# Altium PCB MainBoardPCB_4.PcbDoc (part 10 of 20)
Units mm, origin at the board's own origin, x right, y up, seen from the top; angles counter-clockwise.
Board outline 333.63 x 349.38 mm, 16 copper layers (L1, L2 (GND), L3 (Sign), L4 (GND), L5 (Sign), L6 (PWR/GND), L7(PWR/GND), L8 (Plane_GND), L9 (PWR/GND), L10 (PWR/GND), L11 (PWR/GND), L12 (Sign), L13 (GND), L14 (Sign), L15 (GND), L16), stack 2.502 mm thick; 2205 components, 1648 nets, 8314 pads, 3172 vias.
Unrouted connection lines stored in the file: 5141.
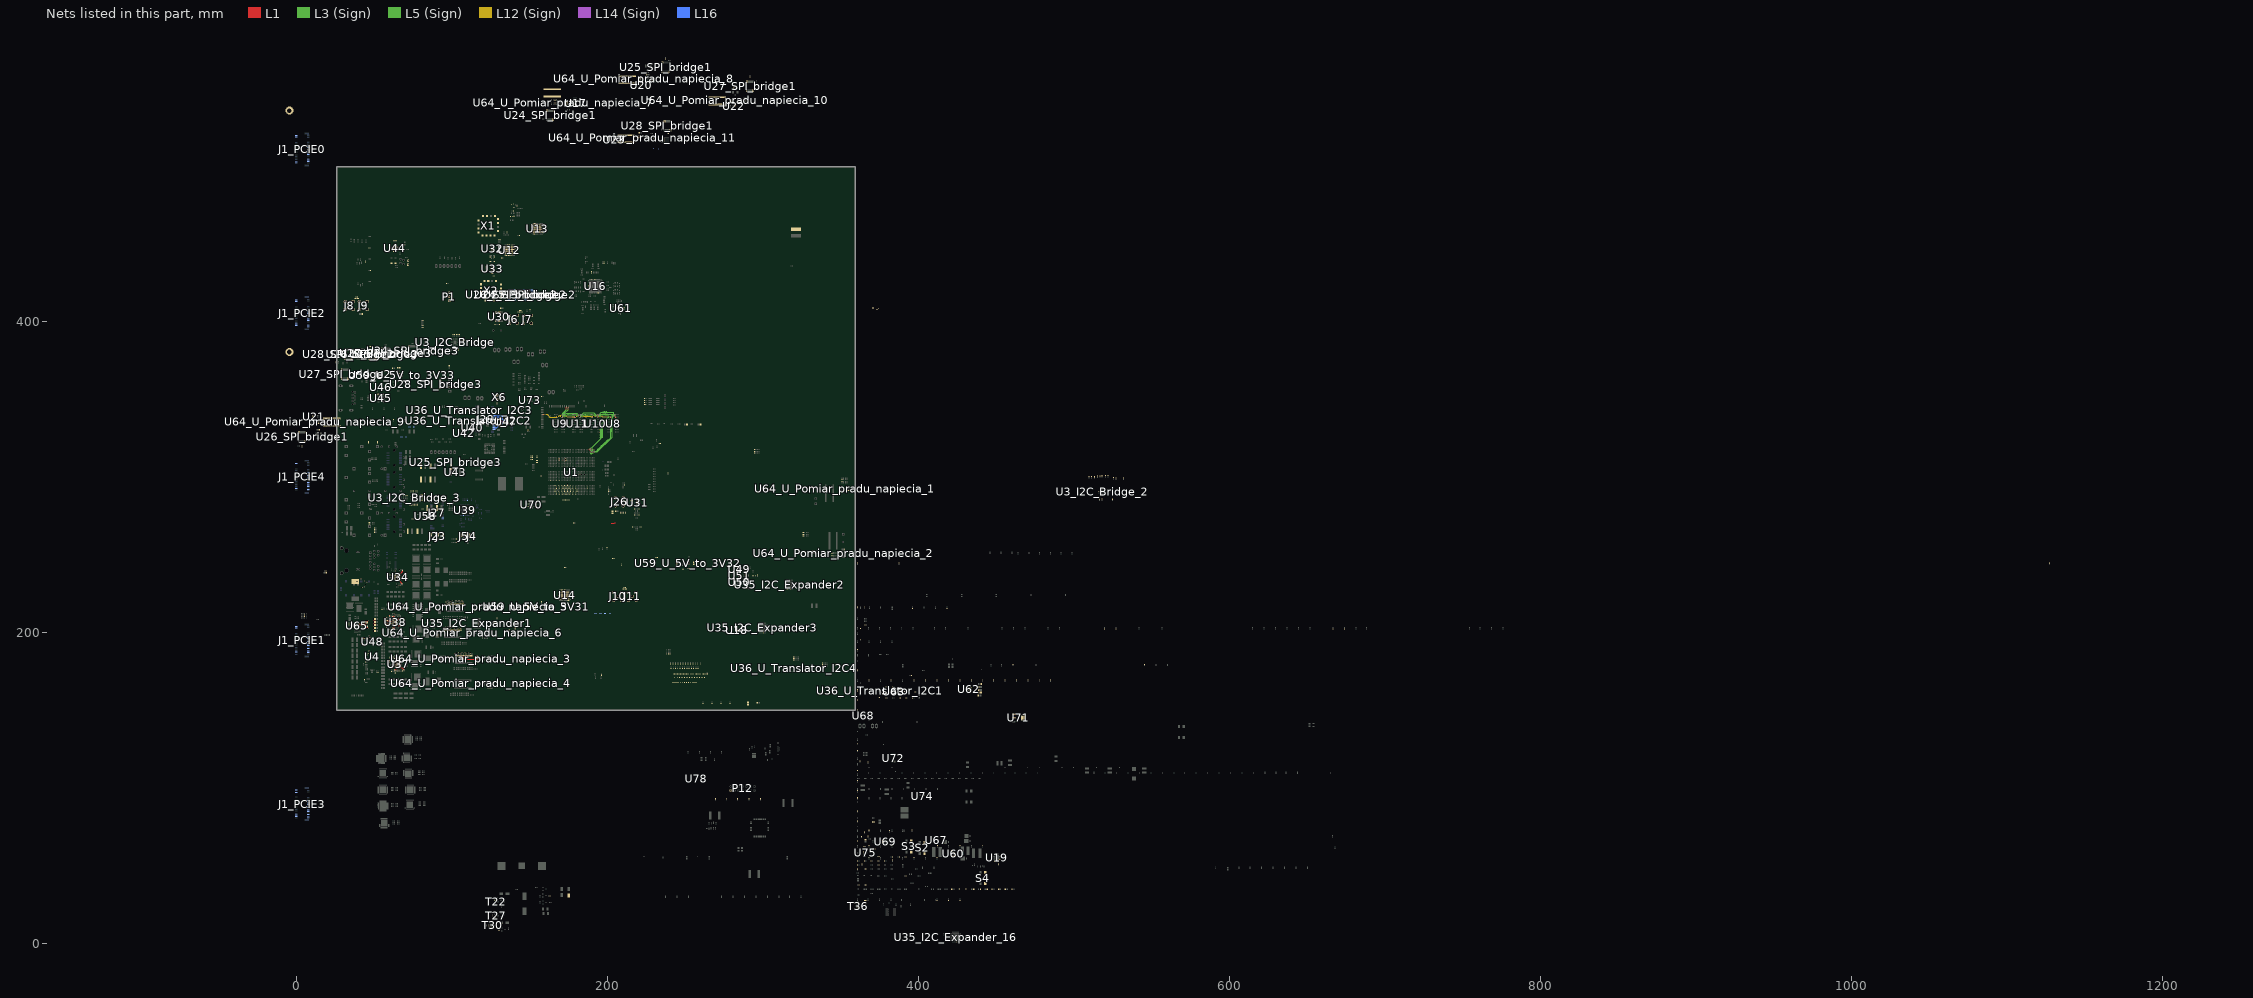
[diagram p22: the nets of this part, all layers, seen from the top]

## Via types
v1: diameter 0.5, hole 0.2, L1 to L16, tented both sides, 1153 vias
v2: diameter 0.5/0.35/0.35/0.35/0.35/0.35/0.35/0.35/0.35/0.35/0.35/0.35/0.35/0.35/0.35/0.5 (per signal layer), hole 0.2, L1 to L16, tented both sides, 548 vias
v3: diameter 0.5, hole 0.2, L1 to L16, 522 vias
v4: diameter 0.5/0.35/0.35/0.35/0.35/0.35/0.35/0.35/0.35/0.35/0.35/0.35/0.35/0.35/0.35/0.5 (per signal layer), hole 0.15, L1 to L16, tented both sides, 266 vias
v5: diameter 0.8, hole 0.4, L1 to L16, tented both sides, 164 vias
v6: diameter 0.35/0/0.35 (per signal layer), hole 0.127, L1 to L3 (Sign), tented both sides, 132 vias
v7: diameter 2.54, hole 1.02, L1 to L16, 125 vias
v8: diameter 1.4, hole 0.5, L1 to L16, tented both sides, 80 vias
v9: diameter 0.35, hole 0.127, L1 to L2 (GND), tented both sides, 36 vias
v10: diameter 0.4, hole 0.2, L1 to L16, 16 vias
v11: diameter 0.25, hole 0.2, L1 to L16, 16 vias
v12: diameter 5, hole 3, L1 to L16, 15 vias
v13: diameter 0.3, hole 0.2, L1 to L16, 15 vias
v14: diameter 0.45, hole 0.15, L1 to L16, 12 vias
v15: diameter 0.5/0.35/0.35/0.35/0.35/0.35/0.35/0.35/0.35/0.35/0.35/0.35/0.35/0.35/0.35/0.45 (per signal layer), hole 0.15, L1 to L16, tented both sides, 10 vias
v16: diameter 0.2/0/0.2 (per signal layer), hole 0.1, L1 to L3 (Sign), tented both sides, 9 vias
v17: diameter 0.4, hole 0.1, L1 to L16, 7 vias
v18: diameter 0.5, hole 0.2, L3 (Sign) to L6 (PWR/GND), tented both sides, 6 vias
v19: diameter 1.65, hole 1.65, L1 to L16, 6 vias
v20: diameter 1.15, hole 1.15, L1 to L16, 6 vias
v21: diameter 0.35/0/0.35 (per signal layer), hole 0.127, L14 (Sign) to L16, tented both sides, 5 vias
v22: diameter 0.2, hole 0.1, L1 to L16, 4 vias
v23: diameter 0.4, hole 0.2, L1 to L16, tented both sides, 2 vias
v24: diameter 0.4, hole 0.15, L1 to L16, 2 vias
v25: diameter 0.508, hole 0.127, L1 to L2 (GND), 2 vias
v26: diameter 0.508, hole 0.127, L2 (GND) to L3 (Sign), 2 vias
v27: diameter 0.5/0.35/0.35/0.35/0.35/0.35/0.35/0.35/0.35/0.35/0.35/0.35/0.35/0.35/0.35/0.5 (per signal layer), hole 0.15, L1 to L16, 2 vias
v28: diameter 0.35, hole 0.127, L3 (Sign) to L6 (PWR/GND), tented both sides, 2 vias
v29: diameter 5.5, hole 3.5, L1 to L16, 1 vias
v30: diameter 0.5/0.35/0.35/0.35/0.35/0.35/0.35/0.35/0.35/0.35/0.35/0.35/0.35/0.35/0.35/0.5 (per signal layer), hole 0.2, L1 to L16, 1 vias
v31: diameter 0.35/0.35/0.35 (per signal layer), hole 0.127, L1 to L3 (Sign), tented both sides, 1 vias
v32: diameter 0.45/0/0.45 (per signal layer), hole 0.15, L1 to L3 (Sign), tented both sides, 1 vias
v33: diameter 0.45/0/0.45 (per signal layer), hole 0.2, L14 (Sign) to L16, tented both sides, 1 vias
v34: diameter 0.35, hole 0.127, L2 (GND) to L3 (Sign), 1 vias
v35: diameter 0.35, hole 0.127, L1 to L2 (GND), 1 vias

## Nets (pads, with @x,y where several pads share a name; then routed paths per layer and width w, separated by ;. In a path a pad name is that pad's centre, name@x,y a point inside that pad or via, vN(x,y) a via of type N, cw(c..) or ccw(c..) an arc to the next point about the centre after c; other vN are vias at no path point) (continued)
3V3_RAIL: C303_I2C_Bridge.2 C303_I2C_Bridge_2.2 C303_I2C_Bridge_3.2 C309_U_Pomiar_pradu_napiecia_1.2 C309_U_Pomiar_pradu_napiecia_2.2 C309_U_Pomiar_pradu_napiecia_3.2 C309_U_Pomiar_pradu_napiecia_4.2 C309_U_Pomiar_pradu_napiecia_5.2 C309_U_Pomiar_pradu_napiecia_6.2 C309_U_Pomiar_pradu_napiecia_7.2 C309_U_Pomiar_pradu_napiecia_8.2 C309_U_Pomiar_pradu_napiecia_9.2 C309_U_Pomiar_pradu_napiecia_10.2 C309_U_Pomiar_pradu_napiecia_11.2 C310.2 C311_I2C_Expander1.2 C311_I2C_Expander2.2 C311_I2C_Expander3.2 C311_I2C_Expander?.2 C311_I2C_Expander_10.2 C311_I2C_Expander_11.2 C311_I2C_Expander_12.2 C311_I2C_Expander_13.2 C311_I2C_Expander_14.2 C311_I2C_Expander_15.2 C311_I2C_Expander_16.2 C324.2 C331.2 C339.2 C545.2 C546.2 C550.2 C552.2 C554.2 C562.2 C585.2 C623.2 C654.2 C676.2 C707.2 C708.2 C721.2 C732.2 C735.2 C792.2 FB1_PCIE0.2 FB1_PCIE1.2 FB1_PCIE2.2 FB1_PCIE3.2 FB1_PCIE4.2 FB23.1 FB24.1 J1_PCIE0.6 J1_PCIE0.8 J1_PCIE0.10 J1_PCIE1.6 J1_PCIE1.8 J1_PCIE1.10 J1_PCIE2.6 J1_PCIE2.8 J1_PCIE2.10 J1_PCIE3.6 J1_PCIE3.8 J1_PCIE3.10 J1_PCIE4.6 J1_PCIE4.8 J1_PCIE4.10 J28.4 L1.1 L2.1 L3.1 L4.1 L5.1 L6.1 L7.1 L8.1 P12.1 R3_I2C_Bridge.2 R3_I2C_Bridge_2.2 R3_I2C_Bridge_3.2 R4_I2C_Bridge.2 R4_I2C_Bridge_2.2 R4_I2C_Bridge_3.2 R5_I2C_Bridge.2 R5_I2C_Bridge_2.2 R5_I2C_Bridge_3.2 R6_I2C_Bridge.2 R6_I2C_Bridge_2.2 R6_I2C_Bridge_3.2 R7_I2C_Bridge.2 R7_I2C_Bridge_2.2 R7_I2C_Bridge_3.2 R8_I2C_Bridge.2 R8_I2C_Bridge_2.2 R8_I2C_Bridge_3.2 R9_I2C_Bridge.2 R9_I2C_Bridge_2.2 R9_I2C_Bridge_3.2 R10_I2C_Bridge.2 R10_I2C_Bridge_2.2 R10_I2C_Bridge_3.2 R11.1 R13.1 R16.1 R29.2 R30.2 R65.2 R66.2 R67.2 R68.2 R71.2 R72.2 R124.2 R175.1 R179.1 R184.1 R188.1 R193.1 R197.1 R202.1 R206.1 R211.1 R219.1 R223_I2C_Bridge.2 R223_I2C_Bridge_2.2 R223_I2C_Bridge_3.2 R224_I2C_Bridge.2 R224_I2C_Bridge_2.2 R224_I2C_Bridge_3.2 R225_I2C_Bridge.2 R225_I2C_Bridge_2.2 R225_I2C_Bridge_3.2 R226_I2C_Bridge.2 R226_I2C_Bridge_2.2 R226_I2C_Bridge_3.2 R227_I2C_Bridge.2 R227_I2C_Bridge_2.2 R227_I2C_Bridge_3.2 R230.1 R231_SPI_bridge1.2 R231_SPI_bridge2.2 R233_SPI_bridge1.2 R233_SPI_bridge2.2 R233_SPI_bridge3.2 R236_SPI_bridge1.2 R236_SPI_bridge2.2 R236_SPI_bridge3.2 R238_SPI_bridge1.2 R240_SPI_bridge1.2 R240_SPI_bridge2.2 R241.2 R243.2 R252.2 R253.2 R281.2 R287.2 R376.2 R377.2 R378.2 R388.1 R425.2 R426.2 R427.2 R428.2 R429.2 R448_U_Pomiar_pradu_napiecia_3.2 R449.2 R451.2 R453.2 R455.2 R458.2 R462.2 R463.1 R468.1 R469.2 R471.2 R473.2 R475.2 R477.2 R479.2 R492.2 R494.2 R496.2 R500.2 R502.2 R504.2 R508.2 R510.2 R512.2 R516.2 R518.2 R520.2 R524.2 R526.2 R528.2 R538.2 R558_I2C_Bridge.2 R558_I2C_Bridge_2.2 R558_I2C_Bridge_3.2 R559_I2C_Bridge.2 R559_I2C_Bridge_2.2 R559_I2C_Bridge_3.2 R560_I2C_Bridge.2 R560_I2C_Bridge_2.2 R560_I2C_Bridge_3.2 R562.1 R566.1 R570.1 R574.1 R578.1 R582.1 R586.1 R590.1 R596.1 R599.2 R600.2 R602.1 R603.1 R604.1 R605.1 R606.1 R630.1 R632.2 R633.2 R634.2 R646.1 R649.1 R676.2 R691.1 R697.2 R699.2 R701.2 R703.2 R705.2 R707.2 R730.2 R731.2 R732.2 R733.2 R734.2 R738.2 R740.2 R742.2 R746.2 R747.2 R748.2 R749.2 R750.2 R751.2 R752.2 R753.2 R754.2 R755.2 R756.2 R757.2 R758.2 R760.2 R762.2 R832.1 R833.1 R834.1 R835.1 U3_I2C_Bridge.21 U3_I2C_Bridge_2.21 U3_I2C_Bridge_3.21 U15.15 U18.C3 U18.D3 U18.D4 U18.E3 U18.E4 U18.F3 U18.F4 U19.13 U19.16 U24_SPI_bridge1.1 U24_SPI_bridge1.7 U24_SPI_bridge1.8 U24_SPI_bridge1.15 U24_SPI_bridge1.16 U24_SPI_bridge2.1 U24_SPI_bridge2.7 U24_SPI_bridge2.8 U24_SPI_bridge2.15 U24_SPI_bridge2.16 U24_SPI_bridge3.1 U24_SPI_bridge3.7 U24_SPI_bridge3.8 U24_SPI_bridge3.16 U25_SPI_bridge1.1 U25_SPI_bridge1.7 U25_SPI_bridge1.8 U25_SPI_bridge1.15 U25_SPI_bridge1.16 U25_SPI_bridge2.1 U25_SPI_bridge2.7 U25_SPI_bridge2.8 U25_SPI_bridge2.15 U25_SPI_bridge2.16 U25_SPI_bridge3.1 U25_SPI_bridge3.7 U25_SPI_bridge3.8 U25_SPI_bridge3.15 U25_SPI_bridge3.16 U26_SPI_bridge1.1 U26_SPI_bridge1.7 U26_SPI_bridge1.8 U26_SPI_bridge1.15 U26_SPI_bridge1.16 U26_SPI_bridge2.1 U26_SPI_bridge2.7 U26_SPI_bridge2.8 U26_SPI_bridge2.15 U26_SPI_bridge2.16 U26_SPI_bridge3.1 U26_SPI_bridge3.7 U26_SPI_bridge3.8 U26_SPI_bridge3.15 U26_SPI_bridge3.16 U27_SPI_bridge1.1 U27_SPI_bridge1.7 U27_SPI_bridge1.8 U27_SPI_bridge1.15 U27_SPI_bridge1.16 U27_SPI_bridge2.1 U27_SPI_bridge2.7 U27_SPI_bridge2.8 U27_SPI_bridge2.16 U27_SPI_bridge3.1 U27_SPI_bridge3.7 U27_SPI_bridge3.8 U27_SPI_bridge3.16 U28_SPI_bridge1.1 U28_SPI_bridge1.7 U28_SPI_bridge1.8 U28_SPI_bridge1.15 U28_SPI_bridge1.16 U28_SPI_bridge2.1 U28_SPI_bridge2.7 U28_SPI_bridge2.8 U28_SPI_bridge2.15 U28_SPI_bridge2.16 U28_SPI_bridge3.1 U28_SPI_bridge3.7 U28_SPI_bridge3.8 U28_SPI_bridge3.16 U35_I2C_Expander1.5 U35_I2C_Expander2.5 U35_I2C_Expander3.5 U35_I2C_Expander_16.5 U36_U_Translator_I2C1.7 U36_U_Translator_I2C2.2 U36_U_Translator_I2C2.7 U36_U_Translator_I2C3.2 U36_U_Translator_I2C3.7 U36_U_Translator_I2C4.7 U45.32 U47.A4 U49.1 U49.2 U50.1 U50.2 U51.1 U51.2 U58.5 U63.3 U64_U_Pomiar_pradu_napiecia_1.6 U64_U_Pomiar_pradu_napiecia_2.6 U64_U_Pomiar_pradu_napiecia_3.6 U64_U_Pomiar_pradu_napiecia_3.8 U64_U_Pomiar_pradu_napiecia_3.9 U64_U_Pomiar_pradu_napiecia_4.6 U64_U_Pomiar_pradu_napiecia_5.6 U64_U_Pomiar_pradu_napiecia_6.6 U64_U_Pomiar_pradu_napiecia_7.6 U64_U_Pomiar_pradu_napiecia_8.6 U64_U_Pomiar_pradu_napiecia_9.6 U64_U_Pomiar_pradu_napiecia_10.6 U64_U_Pomiar_pradu_napiecia_11.6 U67.1 U68.1 U69.1 U69.2 U69.3 U69.15 U69.16 U70.1 U70.2 U70.4 U70.5 U72.6 U73.2 U74.5 U78.5 | length 12.5
  L1 w0.254: U64_U_Pomiar_pradu_napiecia_3.9@116.278,182.659 U64_U_Pomiar_pradu_napiecia_3.8@116.278,183.159 ; U64_U_Pomiar_pradu_napiecia_3.6@116.278,184.159 116.278,184.858 v5(116.281,184.861)
  L1 w0.3: R448_U_Pomiar_pradu_napiecia_3.2@107.759,184.901 107.759,183.101 108.201,182.659 U64_U_Pomiar_pradu_napiecia_3.9@116.278,182.659
  L1 w0.5: v5(52.018,192.237) R630.1@52.018,193.051
  other v5: 112.903,186.048 109.306,186.088 111.104,186.068 107.508,186.109 105.71,186.129 103.911,186.149 102.113,186.169 110.215,186.977 112.014,186.957 108.417,186.998 106.619,187.018 103.022,187.058 104.821,187.038
  other v12: -4.475,380.276
5V_LN: C580.2 R443.2 R608.2 U12.42 U30.1 U30.5 U62.9 U62.10 X2.14
5V_RAIL: C515.2 C516.2 C563_U_5V_to_3V31.2 C563_U_5V_to_3V32.2 C563_U_5V_to_3V33.2 C564_U_5V_to_3V31.2 C564_U_5V_to_3V32.2 C564_U_5V_to_3V33.2 C574.2 C575.2 C720.2 C728.2 C733.2 D23.2 R315.2 R448_U_Pomiar_pradu_napiecia_6.2 R651.2 R656.2 T22.1 T27.2 T30.2 U40.1 U40.2 U40.3 U42.1 U42.2 U42.3 U45.21 U46.C3 U46.D3 U46.D4 U46.E3 U46.E4 U46.F3 U46.F4 U59_U_5V_to_3V31.1 U59_U_5V_to_3V31.2 U59_U_5V_to_3V32.1 U59_U_5V_to_3V32.2 U59_U_5V_to_3V33.1 U59_U_5V_to_3V33.2 U61.1 U61.2 U61.4 U61.5 U64_U_Pomiar_pradu_napiecia_6.8 U64_U_Pomiar_pradu_napiecia_6.9 U73.1
  other v5: 105.778,202.507 102.181,202.548 103.98,202.527 100.383,202.568 98.585,202.588 96.787,202.608 94.988,202.629 103.091,203.437 104.889,203.416 101.292,203.457 99.494,203.477 95.898,203.517 97.696,203.497
12V_HiSpeed: C304.1 C305.1 C306.1 C307.1 C604.2 C714.2 FB34.1 L15.1 R448_U_Pomiar_pradu_napiecia_5.2 R626.2 U17.C3 U17.D3 U17.D4 U17.E3 U17.E4 U17.F3 U17.F4 U19.9 U19.11 U19.26 U19.28 U20.C3 U20.D3 U20.D4 U20.E3 U20.E4 U20.F3 U20.F4 U21.C3 U21.D3 U21.D4 U21.E3 U21.E4 U21.F3 U21.F4 U22.C3 U22.D3 U22.D4 U22.E3 U22.E4 U22.F3 U22.F4 U23.C3 U23.D3 U23.D4 U23.E3 U23.E4 U23.F3 U23.F4 U64_U_Pomiar_pradu_napiecia_5.8 U64_U_Pomiar_pradu_napiecia_5.9 U71.1 | length 0.4
  L1 w0.254: R626.2@59.997,210.611 59.997,210.961
  other v5: 107.235,219.335 105.437,219.355 103.638,219.375 100.042,219.416 101.84,219.395 98.244,219.436 96.446,219.456 106.346,220.244 104.548,220.264 100.951,220.305 102.749,220.284 99.153,220.325 97.355,220.345
12V_PCIE0: R448_U_Pomiar_pradu_napiecia_7.1 U17.C2 U17.D1 U17.D2 U17.E1 U17.E2 U17.F1 U17.F2 U64_U_Pomiar_pradu_napiecia_7.10
12V_PCIE1: R448_U_Pomiar_pradu_napiecia_8.1 U20.C2 U20.D1 U20.D2 U20.E1 U20.E2 U20.F1 U20.F2 U64_U_Pomiar_pradu_napiecia_8.10
12V_PCIE2: R448_U_Pomiar_pradu_napiecia_9.1 U21.C2 U21.D1 U21.D2 U21.E1 U21.E2 U21.F1 U21.F2 U64_U_Pomiar_pradu_napiecia_9.10
12V_PCIE3: R448_U_Pomiar_pradu_napiecia_10.1 U22.C2 U22.D1 U22.D2 U22.E1 U22.E2 U22.F1 U22.F2 U64_U_Pomiar_pradu_napiecia_10.10
12V_PCIE4: R448_U_Pomiar_pradu_napiecia_11.1 U23.C2 U23.D1 U23.D2 U23.E1 U23.E2 U23.F1 U23.F2 U64_U_Pomiar_pradu_napiecia_11.10
+12V_PCIE0: J1_PCIE0.60 J1_PCIE0.62 J1_PCIE0.64 J1_PCIE0.66 R448_U_Pomiar_pradu_napiecia_7.2 U64_U_Pomiar_pradu_napiecia_7.8 U64_U_Pomiar_pradu_napiecia_7.9
+12V_PCIE1: J1_PCIE1.60 J1_PCIE1.62 J1_PCIE1.64 J1_PCIE1.66 R448_U_Pomiar_pradu_napiecia_8.2 U64_U_Pomiar_pradu_napiecia_8.8 U64_U_Pomiar_pradu_napiecia_8.9
+12V_PCIE2: J1_PCIE2.60 J1_PCIE2.62 J1_PCIE2.64 J1_PCIE2.66 R448_U_Pomiar_pradu_napiecia_9.2 U64_U_Pomiar_pradu_napiecia_9.8 U64_U_Pomiar_pradu_napiecia_9.9
+12V_PCIE3: J1_PCIE3.60 J1_PCIE3.62 J1_PCIE3.64 J1_PCIE3.66 R448_U_Pomiar_pradu_napiecia_10.2 U64_U_Pomiar_pradu_napiecia_10.8 U64_U_Pomiar_pradu_napiecia_10.9
+12V_PCIE4: J1_PCIE4.60 J1_PCIE4.62 J1_PCIE4.64 J1_PCIE4.66 R448_U_Pomiar_pradu_napiecia_11.2 U64_U_Pomiar_pradu_napiecia_11.8 U64_U_Pomiar_pradu_napiecia_11.9
\I\N\T\: R709.2 U39.44
\M\R\: D11.1 D12.1 P5.1 R371.1 U44.13
ADP1741_3.6V: C308.2 C354.2 C355.2 C570.2 C603.2 L13.2 R113.2 U60.1 U60.2 U60.3 U60.15 U60.16
ADP1741_EN: U35_I2C_Expander2.18 U60.4
ADP1741_PG: U35_I2C_Expander2.2 U60.5
ADP_Vin_1: C395.2 R285.2 U37.3
ADP_Vin_2: C436.2 R303.2 U38.3 | length 2.8
  L1 w0.254: C436.2@58.746,207.523 59.82,207.523 60.129,207.214 U38.3@61.453,207.214
AGND: C45.1 C46.1 C55.1 C56.1 C57.1 C58.1 C59.1 C60.1 C61.1 C62.1 C65.1 C66.1 C68.1 C69.1 C71.1 C72.1 C73.1 C74.1 C84.1 C85.1 C86.1 C87.1 C94.1 C95.1 C97.1 C98.1 C111.1 C112.1 C113.1 C114.1 C115.1 C116.1 C117.1 C118.1 C119.1 C120.1 C121.1 C122.1 C123.1 C128.1 C129.1 C130.1 C131.1 C132.1 C133.1 C134.1 C135.1 C136.1 C137.1 C138.1 C139.1 C140.1 C149.1 C150.1 C151.1 C152.1 C153.1 C154.1 C155.1 C156.1 C157.1 C158.1 C159.1 C160.1 C161.1 C166.1 C167.1 C168.1 C169.1 C170.1 C171.1 C172.1 C173.1 C174.1 C175.1 C176.1 C177.1 C178.1 C181.1 C182.1 C183.1 C184.1 C185.1 C186.1 C187.1 C188.1 C189.1 C190.1 C191.1 C192.1 C193.1 C194.1 C195.1 C196.1 C197.1 C198.1 C199.1 C200.1 C201.1 C202.1 C203.1 C204.1 C205.1 C206.1 C322.1 C323.1 C324.1 C326.1 C327.1 C328.1 C329.1 C335.1 C336.1 C337.1 C338.1 C339.1 C340.1 C344.2 C563_U_5V_to_3V31.1 C563_U_5V_to_3V32.1 C563_U_5V_to_3V33.1 C564_U_5V_to_3V31.1 C564_U_5V_to_3V32.1 C564_U_5V_to_3V33.1 C565_U_5V_to_3V31.1 C565_U_5V_to_3V32.1 C565_U_5V_to_3V33.1 C566_U_5V_to_3V31.1 C566_U_5V_to_3V32.1 C566_U_5V_to_3V33.1 C567_U_5V_to_3V31.1 C567_U_5V_to_3V32.1 C567_U_5V_to_3V33.1 C568.1 C569.1 C570.1 C571.2 C580.1 C581.1 C582.1 C583.1 C584.1 C713.1 C714.1 FB35.2 J2.1 J2.3 J3.1 J3.3 J4.1 J4.3 J5.1 J5.3 J6.2 J6.3 J6.4 J6.5 J7.2 J7.3 J7.4 J7.5 J8.2 J8.3 J8.4 J8.5 J9.2 J9.3 J9.4 J9.5 J10.2 J10.3 J10.4 J10.5 J11.2 J11.3 J11.4 J11.5 J26.2 J26.3 J26.4 J26.5 R246.1 R247.1 R248.1 R249.2 R254.1 R255.1 R256.1 R258.2 R261.1 R262.1 R263.1 R264.1 R265.1 R291.2 R301.2 R387.1 R432_U_5V_to_3V31.1 R432_U_5V_to_3V32.1 R432_U_5V_to_3V33.1 R434.1 R444.1 R445.1 R482.2 R483.2 R487.1 R536.2 R537.1 R609.1 T36.2 U12.36 U12.41 U12.53 U13.36 U13.41 U13.53 U14.36 U14.41 U14.53 U31.1 U31.2 U31.17 U32.1 U32.17 U33.5 U33.6 U33.14 U33.17 U59_U_5V_to_3V31.4 U59_U_5V_to_3V31.9 U59_U_5V_to_3V32.4 U59_U_5V_to_3V32.9 U59_U_5V_to_3V33.4 U59_U_5V_to_3V33.9 U60.6 U60.17 U62.5 U62.8 U62.11 U71.2 X1.1 X1.3 X1.4 X1.5 X1.6 X1.7 X1.8 X1.9 X1.11 X1.12 X1.13 X1.15 X1.16
  other v3: 421.804,57.122 422.904,57.122 421.804,58.222 422.904,58.222 431.927,162.814 432.689,162.814 431.927,163.576 432.689,163.576 431.927,164.338 432.689,164.338 153.862,215.991 154.862,215.991 153.862,216.991 154.862,216.991 169.726,221.726 170.826,221.726 171.926,221.726 173.026,221.726 174.126,221.726 175.226,221.726 169.726,222.826 170.826,222.826 171.926,222.826 173.026,222.826 174.126,222.826 175.226,222.826 169.726,223.926 170.826,223.926 171.926,223.926 173.026,223.926 174.126,223.926 175.226,223.926 169.726,225.026 170.826,225.026 171.926,225.026 173.026,225.026 174.126,225.026 175.226,225.026 169.726,226.126 170.826,226.126 171.926,226.126 173.026,226.126 174.126,226.126 175.226,226.126 251.341,243.886 252.341,243.886 251.341,244.886 252.341,244.886 67.28,364.904 68.28,364.904 67.28,365.904 68.28,365.904 134.296,443.43 135.396,443.43 136.496,443.43 137.596,443.43 138.696,443.43 139.796,443.43 134.296,444.53 135.396,444.53 136.496,444.53 137.596,444.53 138.696,444.53 139.796,444.53 134.296,445.63 135.396,445.63 136.496,445.63 137.596,445.63 138.696,445.63 139.796,445.63 134.296,446.73 135.396,446.73 136.496,446.73 137.596,446.73 138.696,446.73 139.796,446.73 134.296,447.83 135.396,447.83 136.496,447.83 137.596,447.83 138.696,447.83 139.796,447.83 152.3,457.342 153.4,457.342 154.5,457.342 155.6,457.342 156.7,457.342 157.8,457.342 152.3,458.442 153.4,458.442 154.5,458.442 155.6,458.442 156.7,458.442 157.8,458.442 152.3,459.542 153.4,459.542 154.5,459.542 155.6,459.542 156.7,459.542 157.8,459.542 152.3,460.642 153.4,460.642 154.5,460.642 155.6,460.642 156.7,460.642 157.8,460.642 152.3,461.742 153.4,461.742 154.5,461.742 155.6,461.742 156.7,461.742 157.8,461.742
  other v10: 125.627,433.289 126.577,433.289 125.627,434.239 126.577,434.239
  other v12: -4.475,535.508
AGND_1: C389.1 C393.1 C395.1 C398.1 C399.1 C639.1 C640.1 C641.1 C642.1 C643.1 C644.1 R290.1 R294.1 R300.1 U37.6 U37.33
  other v3: 64.825,178.017 66.025,178.017 63.875,178.967 64.825,178.967 66.025,178.967 66.975,178.967 63.875,180.167 64.825,180.167 66.025,180.167 66.975,180.167 64.825,181.117 66.025,181.117
AGND_2: C430.1 C434.1 C436.1 C439.1 C440.1 C548.1 C549.1 C647.1 C648.1 C650.1 C652.1 R312.1 R318.1 R627.1 U38.6 U38.33 | length 7.4
  L1 w0.254: R312.1@57.926,204.716 57.926,205.54 57.15,206.316 57.15,207.205 57.468,207.523 C436.1@57.967,207.523 ; 57.937,205.529 59.906,205.529 60.091,205.714 U38.6@61.453,205.714
  other v3: 63.103,204.914 64.303,204.914 62.153,205.864 63.103,205.864 64.303,205.864 65.253,205.864 62.153,207.064 63.103,207.064 64.303,207.064 65.253,207.064 63.103,208.014 64.303,208.014
  other v14: 60.944,210.483 62.953,211.029 63.953,211.044 62.838,212.229
Analog_In5: U1.AD14
  other v2: 185.397,301.539
Analog_In6: U1.AA14
  other v2: 182.397,301.539
Analog_In7: U1.AB14
  other v2: 183.397,301.539
ANGD: C345.1 C349.1 C351.1 C356.1 C357.1 C358.2 C634.1 C635.1 R273.1 U34.6 U34.33
  other v3: 64.472,233.839 65.672,233.839 63.522,234.789 64.472,234.789 65.672,234.789 66.622,234.789 63.522,235.989 64.472,235.989 65.672,235.989 66.622,235.989 64.472,236.939 65.672,236.939
  other v14: 66.055,230.182 64.44,230.197 59.876,233.839 60.241,236.629 63.839,239.52 66.32,240.47
B223_Rx0_N: J1_PCIE0.47 U1.W3
B223_Rx0_P: J1_PCIE0.49 U1.W4
B223_Rx1_N: J1_PCIE0.35 U1.V5
B223_Rx1_P: J1_PCIE0.37 U1.V6
B223_Rx2_N: J1_PCIE1.47 U1.T5
B223_Rx2_P: J1_PCIE1.49 U1.T6
B223_Rx3_N: J1_PCIE1.35 U1.R3
B223_Rx3_P: J1_PCIE1.37 U1.R4
B223_Tx0_to_C_N: C268.1 J1_PCIE0.41
B223_Tx0_to_C_P: C267.1 J1_PCIE0.43
B223_Tx0C_to_B_N: C268.2 U1.V1
B223_Tx0C_to_B_P: C267.2 U1.V2
B223_Tx1_to_C_N: C270.1 J1_PCIE0.29
B223_Tx1_to_C_P: C269.1 J1_PCIE0.31
B223_Tx1C_to_B_N: C270.2 U1.U3
B223_Tx1C_to_B_P: C269.2 U1.U4
B223_Tx2_to_C_N: C272.1 J1_PCIE1.41
B223_Tx2_to_C_P: C271.1 J1_PCIE1.43
B223_Tx2C_to_B_N: C272.2 U1.T1
B223_Tx2C_to_B_P: C271.2 U1.T2
B223_Tx3_to_C_N: C275.1 J1_PCIE1.29
B223_Tx3_to_C_P: C274.1 J1_PCIE1.31
B223_Tx3C_to_B_N: C275.2 U1.P1
B223_Tx3C_to_B_P: C274.2 U1.P2
B224_Rx0_N: J1_PCIE2.47 U1.P5
B224_Rx0_P: J1_PCIE2.49 U1.P6
B224_Rx1_N: J1_PCIE2.35 U1.M5
B224_Rx1_P: J1_PCIE2.37 U1.M6
B224_Rx2_N: J1_PCIE3.47 U1.L3
B224_Rx2_P: J1_PCIE3.49 U1.L4
B224_Rx3_N: J1_PCIE3.35 U1.K5
B224_Rx3_P: J1_PCIE3.37 U1.K6
B224_Tx0_to_C_N: C280.1 J1_PCIE2.41
B224_Tx0_to_C_P: C279.1 J1_PCIE2.43
B224_Tx0C_to_B_N: C280.2 U1.N3
B224_Tx0C_to_B_P: C279.2 U1.N4
B224_Tx1_to_C_N: C282.1 J1_PCIE2.29
B224_Tx1_to_C_P: C281.1 J1_PCIE2.31
B224_Tx1C_to_B_N: C282.2 U1.M1
B224_Tx1C_to_B_P: C281.2 U1.M2
B224_Tx2_to_C_N: C284.1 J1_PCIE3.41
B224_Tx2_to_C_P: C283.1 J1_PCIE3.43
B224_Tx2C_to_B_N: C284.2 U1.K1
B224_Tx2C_to_B_P: C283.2 U1.K2
B224_Tx3_to_C_N: C287.1 J1_PCIE3.29
B224_Tx3_to_C_P: C286.1 J1_PCIE3.31
B224_Tx3C_to_B_N: C287.2 U1.J3
B224_Tx3C_to_B_P: C286.2 U1.J4
B225_Rx0_N: J1_PCIE4.47 U1.H5
B225_Rx0_P: J1_PCIE4.49 U1.H6
B225_Rx1_N: J1_PCIE4.35 U1.G7
B225_Rx1_P: J1_PCIE4.37 U1.G8
B225_Rx2_N: J1_PCIE4.23 U1.F5
B225_Rx2_P: J1_PCIE4.25 U1.F6
  other v2: 167.397,293.539
B225_Rx3_N: J1_PCIE4.11 U1.E7
B225_Rx3_P: J1_PCIE4.13 U1.E8
B225_Tx0_to_C_N: C292.1 J1_PCIE4.41
B225_Tx0_to_C_P: C291.1 J1_PCIE4.43
B225_Tx0C_to_B_N: C292.2 U1.H1
B225_Tx0C_to_B_P: C291.2 U1.H2
B225_Tx1_to_C_N: C294.1 J1_PCIE4.29
B225_Tx1_to_C_P: C293.1 J1_PCIE4.31
B225_Tx1C_to_B_N: C294.2 U1.G3
B225_Tx1C_to_B_P: C293.2 U1.G4
  other v2: 168.397,291.539
B225_Tx2_to_C_N: C296.1 J1_PCIE4.19
B225_Tx2_to_C_P: C295.1 J1_PCIE4.17
B225_Tx2C_to_B_N: C296.2 U1.F1
B225_Tx2C_to_B_P: C295.2 U1.F2
B225_Tx3_to_C_N: C299.1 J1_PCIE4.7
B225_Tx3_to_C_P: C298.1 J1_PCIE4.5
B225_Tx3C_to_B_N: C299.2 U1.E3
B225_Tx3C_to_B_P: C298.2 U1.E4
B503_Ground: C531.2 C532.2 C533.2 C534.2 C535.1 C536.1 P5.2 R358.2 R359.2 R360.2 R361.2 R373.1 R720.2 S2.3 S2.4 S3.3 S3.4 S4.3 S4.4 U43.9 U43.10 U44.4 U44.5 U44.17 X6.2 | length 0.9
  L1 w0.2: C535.1@148.603,330.314 C536.1@149.543,330.314
  other v3: 62.87,446.303 63.97,446.303 62.87,447.403 63.97,447.403
  other v34: 149.073,330.314
  other v35: 149.073,330.314
Bank223_MGTREF0_C_N: C276.1 U1.R7
Bank223_MGTREF0_C_P: C273.1 U1.R8
Bank223_MGTREF1_C_N: C278.1 U1.N7
Bank223_MGTREF1_C_P: C277.1 U1.N8
  other v2: 174.397,295.539
Bank224_MGTREF0_C_N: C288.1 U1.L7
Bank224_MGTREF0_C_P: C285.1 U1.L8
Bank224_MGTREF1_C_N: C290.1 U1.J7
Bank224_MGTREF1_C_P: C289.1 U1.J8
Bank225_MGTREF0_C_N: C300.1 U1.H9
Bank225_MGTREF0_C_P: C297.1 U1.H10
Bank225_MGTREF1_C_N: C302.1 U1.F9
Bank225_MGTREF1_C_P: C301.1 U1.F10
Bank505_MGTRREF0_C_N: C526.2 R69.2 U1.M24 | length 0.7
  L1 w0.116: v2(172.909,311.052) U1.M24@173.397,311.539
Bank505_MGTRREF0_C_P: C525.2 R69.1 U1.M23 | length 0.7
  L1 w0.116: v2(172.909,310.052) U1.M23@173.397,310.539
Bank505_MGTRREF2_C_N: C528.2 R126.2 U1.K24
  other v2: 171.397,311.539
Bank505_MGTRREF2_C_P: C527.2 R126.1 U1.K23
  other v2: 171.397,310.539
Bank505_MGTRREF3_C_N: C530.2 R70.2 U1.H24 | length 0.7
  L1 w0.116: v2(168.909,312.027) U1.H24@169.397,311.539
Bank505_MGTRREF3_C_P: C529.2 R70.1 U1.H23 | length 0.7
  L1 w0.116: v2(168.909,311.027) U1.H23@169.397,310.539
Battery_PWR: P11.1 R679.2 R680.2 U48.2 | length 1.6
  L1 w0.5: R680.2@43.658,195.933 v5(43.658,196.747) ; R679.2@45.775,195.933 v5(45.775,196.747)
  other v5: 46.906,196.145 48.155,196.145 47.566,196.91 46.907,197.647
  other v10: 48.327,194.383
BST1: C346.1 U34.25 | length 2.7
  L1 w0.254: U34.25@66.822,237.639 66.822,237.71 66.824,237.712 66.895,237.712 68.336,239.154 C346.1@68.336,239.69
BST1_1: C390.1 U37.25
BST1_2: C431.1 U38.25 | length 1.7
  L1 w0.254: U38.25@65.453,208.714 66.596,208.714 66.996,209.114 C431.1@67.001,209.114
BST2: C350.1 U34.16 | length 2.6
  L1 w0.254: U34.16@66.822,233.139 66.822,232.556 67.929,231.449 67.929,231.245 C350.1@68.072,231.102
BST2_1: C394.1 U37.16 | length 2.8
  L1 w0.254: U37.16@67.175,177.317 68.028,177.317 69.151,176.194 C394.1@69.151,175.817
BST2_2: C435.1 U38.16 | length 1.7
  L1 w0.254: U38.16@65.453,204.214 66.661,204.214 67.011,203.864 C435.1@67.016,203.864
CAN1_RxD: R798.1 U63.1
CAN1_TxD: R799.1 U63.4
CAN_H: P6.2 R446.2 R447.2 U63.7 U75.2
CAN_L: P6.1 R446.1 R447.1 U63.6 U75.1
CD_H: J28.9 R381.1 R782.1 U47.D3
Charge_CAP_KEY: R658.2
CLK_Fanout_In_N: U1.AF5
CLK_Fanout_In_P: U1.AF6
CLK_GTR_T1_N: C528.1
CLK_GTR_T1_P: C527.1
CLK_GTR_T2_N: C526.1
CLK_GTR_T2_P: C525.1
CLK_GTR_T3_N: C530.1
CLK_GTR_T3_P: C529.1
CLK_Hi_Rail1_N: R270.1 U12.33 U13.38
CLK_Hi_Rail1_P: R270.2 U12.34 U13.37
CLK_Hi_Rail1_SysRef_N: R534.1 U12.30 U13.48
CLK_Hi_Rail1_SysRef_P: R534.2 U12.31 U13.47
CLK_Hi_Rail2_N: R539.1 U12.6 U14.38
CLK_Hi_Rail2_P: R539.2 U12.7 U14.37
CLK_Hi_Rail2_SysRef_N: R535.1 U12.3 U14.48
CLK_Hi_Rail2_SysRef_P: R535.2 U12.4 U14.47
CLK_M_OSC_In: C333.1 R257.2 U33.2 | length 2.7
  L1 w0.116: 202.539,270.281 202.585,270.281 203.543,270.281 204.555,270.281 204.674,270.4 205.194,270.4
CLK_NVME_Conn_N: J27.53 U14.13
CLK_NVME_Conn_P: J27.55 U14.12
CLK_Q223_T1_N: C276.2
CLK_Q223_T1_P: C273.2
CLK_Q224_T1_N: C288.2
CLK_Q224_T1_P: C285.2
CLK_Q225_T1_N: C300.2
CLK_Q225_T1_P: C297.2
CLK_Q226_T1_N: U1.B9
CLK_Q226_T1_P: U1.B10
CLK_SMA0_C_N: C48.2 J6.1
CLK_SMA0_C_P: C47.2 J7.1
CLK_SMA0_N: C48.1 R78.1 U12.9
CLK_SMA0_P: C47.1 R78.2 U12.10
CLK_SMA1_C_N: C50.2 J8.1
CLK_SMA1_C_P: C49.2 J9.1
CLK_SMA1_N: C50.1 R79.1 U13.3
CLK_SMA1_P: C49.1 R79.2 U13.4
CLK_SMA2_C_N: C52.2 J10.1
CLK_SMA2_C_P: C51.2 J11.1
CLK_SMA2_N: C52.1 R80.1 U14.34
CLK_SMA2_P: C51.1 R80.2 U14.33
CLKREF_R: R375.1 X6.3
CLKREQ: J27.52
CMD_SD: J28.3 U47.D4 | length 8
  L14 (Sign) w0.098: v33(129.927,337.233) 131.355,335.804 133.045,335.804 133.445,335.404 133.929,335.404 v21(134.329,335.004)
  L16 w0.098: J28.3@127.237,337.232 v33(129.927,337.233)
COMP1_1: C642.2 R624.2 U37.30 | length 2.7
  L1 w0.254: R624.2@63.175,183.31 63.195,183.29 64.155,183.29 C642.2@64.175,183.27 64.175,182.936 64.675,182.436 U37.30@64.675,181.817
COMP1_2: C548.2 R687.2 U38.30 | length 2.5
  L1 w0.254: R687.2@61.953,210.269 61.963,210.259 62.943,210.259 C548.2@62.953,210.249 U38.30@62.953,208.714
COMP2_1: C641.2 R623.2 U37.11 | length 2.6
  L1 w0.254: R623.2@63.12,175.907 63.14,175.927 64.155,175.927 C641.2@64.175,175.947 64.175,176.323 64.675,176.823 U37.11@64.675,177.317
COMP2_2: C650.2 R631.2 U38.11 | length 2.4
  L1 w0.254: R631.2@61.938,202.723 62.788,202.723 C650.2@62.828,202.764 62.828,203.439 62.953,203.564 U38.11@62.953,204.214
CSN: C694.2 C695.2 C696.2 C697.2 C698.2 C699.2 C700.2 R17.2 R140.2 R150.2 R666.2 U4.2 U65.10 | length 20.6
  L1 w0.254: U65.10@40.6,205.318 43.104,205.318 ; R150.2@43.102,206.468 43.102,205.319 43.104,205.318 ; R666.2@45.266,206.456 45.266,206.112 44.472,205.318 43.104,205.318
  L1 w0.5: R666.2@44.621,206.456 v1(44.621,207.543) ; R666.2@45.266,206.456 v1(45.266,207.543) ; R666.2@45.904,206.456 v1(45.904,207.543) ; v1(49.507,200.659) C699.2@50.594,200.659 ; v1(49.507,201.383) C699.2@50.593,201.383 ; v1(49.507,202.549) C696.2@50.594,202.549 ; v1(49.507,203.273) C696.2@50.593,203.273 ; v1(49.507,204.44) C697.2@50.594,204.44 ; v1(49.507,205.164) C697.2@50.594,205.164 ; v1(49.507,206.33) C695.2@50.594,206.33 ; v1(49.507,207.054) C695.2@50.593,207.054 ; v1(49.507,208.221) C698.2@50.594,208.221 ; v1(49.507,208.944) C698.2@50.594,208.944
  other v5: 46.939,186.483 48.188,186.483 47.599,187.248 46.94,187.985
  other v10: 48.36,184.721
CSP: L22.2 R666.1 U65.9 | length 8.6
  L1 w0.254: U65.9@40.6,204.818 44.43,204.818 45.266,203.981 R666.1@45.266,203.657
  L1 w0.5: v1(44.629,202.57) R666.1@44.629,203.657 ; v1(45.266,202.57) R666.1@45.266,203.657 ; v1(45.912,202.57) R666.1@45.912,203.657
  other v5: 42.02,228.866 43.644,229.333 37.109,230.581 39.58,230.581 44.463,230.811 45.281,232.29 39.025,232.804 43.802,233.108 41.58,234.493
CSU: P1.2 R783.1
CSU_Neg: P1.3 R109.2
CSU_Pos: P1.1 R106.2
D_05028_G0: R540.2 U1.AA15 U16.45
  other v2: 182.397,302.539
D_05028_G0_1: R540.1
D_05028_G3: U16.40
D_05028_G4: U16.41
D_05028_G5: U16.12
D_05028_G6: U16.13
D_05028_S0: U16.55
D_05028_S1: U16.56
DAC1220_Vref: C320.2 R608.1 R609.2 U30.12
DAC_AGND: U30.4 U30.13 X2.1 X2.3 X2.4 X2.5 X2.6 X2.7 X2.8 X2.9 X2.11 X2.12 X2.13 X2.15 X2.16
DAC_OUT: C321.2 U30.11 X2.2
DAC_SPI_CLK: U26_SPI_bridge3.14 U30.16
DAC_SPI_MOSI: R481.1 U26_SPI_bridge3.12 U30.15
DAS/DSS#: J27.10
DATA0_SD: J28.7 U47.D5 | length 7.6
  L16 w0.098: J28.7@127.237,332.832 127.468,333.064 130.429,333.064 131.61,334.244 132.563,334.244 133.324,335.004 U47.D5@133.927,335.004
DATA1_SD: J28.8 U47.E5 | length 7.9
  L16 w0.098: J28.8@127.237,331.732 128.871,331.732 129.876,332.737 130.384,332.737 131.692,334.046 132.797,334.046 133.356,334.604 U47.E5@133.927,334.604
DATA2_SD: J28.1 U47.A5 | length 8.6
  L16 w0.098: J28.1@127.237,339.432 131.629,339.432 132.374,338.687 132.374,337.757 U47.A5@133.927,336.204
DATA3_SD: J28.2 R383.1 U47.B5 | length 7.7
  L16 w0.098: J28.2@127.452,338.336 130.729,338.336 130.975,338.09 130.975,337.798 131.844,336.928 132.556,336.928 133.68,335.804 U47.B5@133.927,335.804
Data_2_RX_PCIE0_N: J1_PCIE0.23
Data_2_RX_PCIE0_P: J1_PCIE0.25
Data_2_RX_PCIE1_N: J1_PCIE1.23
Data_2_RX_PCIE1_P: J1_PCIE1.25
Data_2_RX_PCIE2_N: J1_PCIE2.23
Data_2_RX_PCIE2_P: J1_PCIE2.25
Data_2_RX_PCIE3_N: J1_PCIE3.23
Data_2_RX_PCIE3_P: J1_PCIE3.25
Data_2_TX_PCIE0_N: J1_PCIE0.19
Data_2_TX_PCIE0_P: J1_PCIE0.17
Data_2_TX_PCIE1_N: J1_PCIE1.19
Data_2_TX_PCIE1_P: J1_PCIE1.17
Data_2_TX_PCIE2_N: J1_PCIE2.19
Data_2_TX_PCIE2_P: J1_PCIE2.17
Data_2_TX_PCIE3_N: J1_PCIE3.19
Data_2_TX_PCIE3_P: J1_PCIE3.17
Data_3_RX_PCIE0_N: J1_PCIE0.11
Data_3_RX_PCIE0_P: J1_PCIE0.13
Data_3_RX_PCIE1_N: J1_PCIE1.11
Data_3_RX_PCIE1_P: J1_PCIE1.13
Data_3_RX_PCIE2_N: J1_PCIE2.11
Data_3_RX_PCIE2_P: J1_PCIE2.13
Data_3_RX_PCIE3_N: J1_PCIE3.11
Data_3_RX_PCIE3_P: J1_PCIE3.13
Data_3_TX_PCIE0_N: J1_PCIE0.7
Data_3_TX_PCIE0_P: J1_PCIE0.5
Data_3_TX_PCIE1_N: J1_PCIE1.7
Data_3_TX_PCIE1_P: J1_PCIE1.5
Data_3_TX_PCIE2_N: J1_PCIE2.7
Data_3_TX_PCIE2_P: J1_PCIE2.5
Data_3_TX_PCIE3_N: J1_PCIE3.7
Data_3_TX_PCIE3_P: J1_PCIE3.5
DDR4_A0: R31.1 U1.AH30 U8.P3 U9.P3 U10.P3 U11.P3 | length 101.4
  L1 w0.116: v4(170.472,338.864) U9.P3@170.876,338.46 ; v4(181.933,338.864) U11.P3@182.336,338.46 ; U1.AH30@189.397,317.539 v6(189.884,318.027) ; v4(193.393,338.864) U10.P3@193.797,338.46 ; v15(204.853,338.864) U8.P3@205.257,338.46
  L1 w0.155: v6(174.855,343.555) R31.1@174.855,344.8
  L5 (Sign) w0.092: v4(170.472,338.864) 171.003,338.864 171.42,339.28 173.296,339.28 174.076,340.06 174.498,340.06 174.632,340.06 cw(c174.632,339.971) 174.722,339.971 174.722,339.917 ccw(c174.811,339.917) 174.811,339.828 175.08,339.828 ccw(c175.08,339.917) 175.17,339.917 175.17,339.971 cw(c175.259,339.971) 175.259,340.06 176.111,340.06 180.091,340.06 181.287,338.864 v4(181.933,338.864) 182.528,338.864 182.944,339.28 183.962,339.28 184.742,340.06 185.649,340.06 185.752,340.06 ccw(c185.752,340.13) 185.822,340.13 185.822,340.205 cw(c185.891,340.205) 185.891,340.274 186.099,340.274 cw(c186.099,340.205) 186.168,340.205 186.168,340.06 186.168,339.916 ccw(c186.237,339.916) 186.237,339.847 186.445,339.847 ccw(c186.445,339.916) 186.514,339.916 186.514,339.991 cw(c186.583,339.991) 186.583,340.06 186.944,340.06 191.829,340.06 193.025,338.864 v4(193.393,338.864) 193.902,338.864 194.281,339.242 195.294,339.242 196.17,340.119 196.647,340.119 cw(c196.647,340.029) 196.736,340.029 196.736,339.923 ccw(c196.826,339.923) 196.826,339.833 197.094,339.833 ccw(c197.094,339.923) 197.184,339.923 197.184,340.119 197.184,340.314 cw(c197.273,340.314) 197.273,340.404 197.542,340.404 cw(c197.542,340.314) 197.632,340.314 197.632,340.119 197.632,339.923 ccw(c197.721,339.923) 197.721,339.833 197.99,339.833 ccw(c197.99,339.923) 198.08,339.923 198.08,340.119 198.08,340.314 cw(c198.169,340.314) 198.169,340.404 198.438,340.404 cw(c198.438,340.314) 198.527,340.314 198.527,340.119 198.527,339.923 ccw(c198.617,339.923) 198.617,339.833 198.886,339.833 ccw(c198.886,339.923) 198.975,339.923 198.975,340.119 198.975,340.314 cw(c199.065,340.314) 199.065,340.404 199.333,340.404 cw(c199.333,340.314) 199.423,340.314 199.423,340.119 199.423,339.923 ccw(c199.512,339.923) 199.512,339.833 199.781,339.833 ccw(c199.781,339.923) 199.871,339.923 199.871,340.119 199.871,340.314 cw(c199.96,340.314) 199.96,340.404 200.229,340.404 cw(c200.229,340.314) 200.319,340.314 200.319,340.119 200.319,340.034 ccw(c200.408,340.034) 200.408,339.945 200.677,339.945 ccw(c200.677,340.034) 200.766,340.034 cw(c200.851,340.034) 200.851,340.119 200.99,340.119 203.022,340.119 204.102,339.039 204.678,339.039 v15(204.853,338.864)
  L3 (Sign) w0.092: v4(170.472,338.864) 171.003,338.864 171.739,339.6 171.739,340.77 171.922,340.953 172.538,340.953 172.671,341.085 ; v6(189.884,318.027) 190.395,318.027 190.64,317.782 190.64,317.763 190.692,317.71 ; 190.692,317.709 190.74,317.661 190.74,317.349 190.517,317.125 190.303,317.125 190.081,317.348 189.55,317.348 189.36,317.158 189.36,316.828 189.738,316.449 189.738,315.504 189.479,315.245 189.479,314.952 189.674,314.757 189.7,314.757 189.751,314.706 190.024,314.706 190.452,315.134 190.452,315.263 190.728,315.539 190.896,315.539 191.437,316.081 193.641,316.081 203.086,325.526 203.086,328.902 203.086,329.13 ccw(c202.999,329.13) 202.999,329.217 202.511,329.217 cw(c202.511,329.303) 202.424,329.303 202.424,329.476 cw(c202.511,329.476) 202.511,329.563 203.086,329.563 203.093,329.563 ccw(c203.093,329.649) 203.179,329.649 203.179,329.822 ccw(c203.093,329.822) 203.093,329.909 203.086,329.909 202.981,329.909 cw(c202.981,329.996) 202.894,329.996 202.894,330.169 cw(c202.981,330.169) 202.981,330.255 203.086,330.255 203.093,330.255 ccw(c203.093,330.342) 203.179,330.342 203.179,330.515 ccw(c203.093,330.515) 203.093,330.601 203.086,330.601 202.994,330.601 cw(c202.994,330.688) 202.907,330.688 202.907,330.861 cw(c202.994,330.861) 202.994,330.948 203.086,330.948 203.093,330.948 ccw(c203.093,331.034) 203.179,331.034 203.179,331.207 ccw(c203.093,331.207) 203.093,331.294 203.086,331.294 202.511,331.294 cw(c202.511,331.38) 202.424,331.38 202.424,331.553 cw(c202.511,331.553) 202.511,331.64 203.086,331.64 203.093,331.64 ccw(c203.093,331.727) 203.179,331.727 203.179,331.9 ccw(c203.093,331.9) 203.093,331.986 203.086,331.986 202.511,331.986 cw(c202.511,332.073) 202.424,332.073 202.424,332.246 cw(c202.511,332.246) 202.511,332.332 202.999,332.332 ccw(c202.999,332.419) 203.086,332.419 203.086,332.506 203.128,332.548 203.128,332.856 203.122,332.862 203.122,333.257 203.122,333.337 ccw(c203.023,333.337) 203.023,333.436 202.839,333.436 cw(c202.839,333.536) 202.74,333.536 202.74,333.734 cw(c202.839,333.734) 202.839,333.833 203.122,333.833 203.143,333.833 ccw(c203.143,333.933) 203.242,333.933 203.242,334.131 ccw(c203.143,334.131) 203.143,334.23 203.122,334.23 202.844,334.23 cw(c202.844,334.33) 202.744,334.33 202.744,334.528 cw(c202.844,334.528) 202.844,334.627 203.122,334.627 203.143,334.627 ccw(c203.143,334.727) 203.242,334.727 203.242,334.925 ccw(c203.143,334.925) 203.143,335.024 203.122,335.024 202.844,335.024 cw(c202.844,335.124) 202.745,335.124 202.745,335.322 cw(c202.844,335.322) 202.844,335.421 203.122,335.421 203.143,335.421 ccw(c203.143,335.521) 203.242,335.521 203.242,335.719 ccw(c203.143,335.719) 203.143,335.818 cw(c203.143,335.839) 203.122,335.839 203.122,336.017 203.456,336.351 203.456,339.499 203.949,339.992 204.174,339.992 204.432,339.734 204.432,339.407 204.559,339.28 204.768,339.28 204.853,339.195 v15(204.853,338.864)
  L3 (Sign) w0.151: 172.671,341.085 174.855,343.27 v6(174.855,343.555)
DDR4_A1: R33.1 U1.AG30 U8.P4 U9.P4 U10.P4 U11.P4 | length 100.3
  L1 w0.116: U9.P4@167.676,338.46 168.072,338.857 v4(168.075,338.857) ; U11.P4@179.136,338.46 179.533,338.857 v4(179.535,338.857) ; U1.AG30@188.397,317.539 v6(188.884,318.027) ; U10.P4@190.597,338.46 190.993,338.857 v4(190.995,338.857) v4@190.954,338.815 ; v15(201.646,338.856) U8.P4@202.049,338.453
  L1 w0.155: R33.1@158.737,340.144 v1(159.982,340.144)
  L12 (Sign) w0.092: 165.251,338.46 166.723,338.46 167.356,338.46 167.711,338.815 168.033,338.815 v4(168.075,338.857) ; v4@168.072,338.857 v4(168.075,338.857) ; v4@179.533,338.857 v4(179.535,338.857) ; v15(201.646,338.856) 201.379,338.856 201.058,338.536 196.832,338.536 196.108,339.26 194.843,339.26 194.709,339.26 ccw(c194.709,339.171) 194.62,339.171 194.62,338.947 cw(c194.53,338.947) 194.53,338.858 194.261,338.858 cw(c194.261,338.947) 194.172,338.947 194.172,339.26 194.172,339.573 ccw(c194.082,339.573) 194.082,339.663 193.813,339.663 ccw(c193.813,339.573) 193.724,339.573 193.724,339.26 193.724,339.241 cw(c193.634,339.241) 193.634,339.152 193.366,339.152 cw(c193.366,339.241) 193.276,339.241 193.276,339.26 193.276,339.349 ccw(c193.187,339.349) 193.187,339.439 192.918,339.439 ccw(c192.918,339.349) 192.828,339.349 192.828,339.26 192.828,338.947 cw(c192.739,338.947) 192.739,338.858 192.47,338.858 cw(c192.47,338.947) 192.381,338.947 192.381,339.171 ccw(c192.291,339.171) 192.291,339.26 191.795,339.26 191.636,339.26 191.232,338.857 v4(190.995,338.857) 190.954,338.815 190.632,338.815 190.335,338.518 189.586,338.518 189.24,338.864 187.088,338.864 186.984,338.864 ccw(c186.984,338.795) 186.914,338.795 186.914,338.77 cw(c186.845,338.77) 186.845,338.701 186.637,338.701 cw(c186.637,338.77) 186.568,338.77 186.568,338.864 186.568,338.97 ccw(c186.499,338.97) 186.499,339.04 186.291,339.04 ccw(c186.291,338.97) 186.222,338.97 186.222,338.864 186.222,338.77 cw(c186.153,338.77) 186.153,338.701 185.945,338.701 cw(c185.945,338.77) 185.876,338.77 185.876,338.864 185.876,338.97 ccw(c185.807,338.97) 185.807,339.04 185.599,339.04 ccw(c185.599,338.97) 185.53,338.97 185.53,338.933 cw(c185.46,338.933) 185.46,338.864 185.204,338.864 184.935,338.864 184.633,339.166 183.804,339.166 183.715,339.255 180.886,339.255 180.488,338.857 v4(179.535,338.857) ; v4(168.075,338.857) 168.651,338.857 169.055,339.26 169.189,339.26 ccw(c169.189,339.35) 169.279,339.35 169.279,339.404 cw(c169.368,339.404) 169.368,339.493 169.637,339.493 cw(c169.637,339.404) 169.727,339.404 169.727,339.26 169.727,339.117 ccw(c169.816,339.117) 169.816,339.027 170.085,339.027 ccw(c170.085,339.117) 170.175,339.117 170.175,339.171 cw(c170.264,339.171) 170.264,339.26 170.472,339.26 173.402,339.26 174.126,338.536 179.214,338.536 v4(179.535,338.857)
  L12 (Sign) w0.151: v1(159.982,340.144) 161.387,340.144 163.071,338.46 165.251,338.46
  L3 (Sign) w0.092: v6(188.884,318.027) 189.551,318.694 189.968,318.694 195.968,324.694 195.968,324.965 195.968,325.064 ccw(c195.869,325.064) 195.869,325.164 195.517,325.164 cw(c195.517,325.263) 195.418,325.263 195.418,325.461 cw(c195.517,325.461) 195.517,325.561 195.968,325.561 196.862,325.561 ccw(c196.862,325.66) 196.961,325.66 196.961,325.858 ccw(c196.862,325.858) 196.862,325.958 195.968,325.958 195.517,325.958 cw(c195.517,326.057) 195.418,326.057 195.418,326.255 cw(c195.517,326.255) 195.517,326.355 195.968,326.355 196.874,326.355 ccw(c196.874,326.454) 196.974,326.454 196.974,326.652 ccw(c196.874,326.652) 196.874,326.752 195.968,326.752 195.517,326.752 cw(c195.517,326.851) 195.418,326.851 195.418,327.049 cw(c195.517,327.049) 195.517,327.149 195.968,327.149 196.874,327.149 ccw(c196.874,327.248) 196.974,327.248 196.974,327.446 ccw(c196.874,327.446) 196.874,327.546 195.968,327.546 195.517,327.546 cw(c195.517,327.645) 195.418,327.645 195.418,327.843 cw(c195.517,327.843) 195.517,327.943 195.968,327.943 196.874,327.943 ccw(c196.874,328.042) 196.974,328.042 196.974,328.24 ccw(c196.874,328.24) 196.874,328.34 195.968,328.34 195.517,328.34 cw(c195.517,328.439) 195.418,328.439 195.418,328.637 cw(c195.517,328.637) 195.517,328.737 195.968,328.737 196.874,328.737 ccw(c196.874,328.836) 196.974,328.836 196.974,329.034 ccw(c196.874,329.034) 196.874,329.134 195.968,329.134 195.517,329.134 cw(c195.517,329.233) 195.418,329.233 195.418,329.431 cw(c195.517,329.431) 195.517,329.531 195.968,329.531 196.874,329.531 ccw(c196.874,329.63) 196.974,329.63 196.974,329.828 ccw(c196.874,329.828) 196.874,329.928 195.968,329.928 195.517,329.928 cw(c195.517,330.027) 195.418,330.027 195.418,330.225 cw(c195.517,330.225) 195.517,330.325 195.968,330.325 196.874,330.325 ccw(c196.874,330.424) 196.974,330.424 196.974,330.622 ccw(c196.874,330.622) 196.874,330.722 195.968,330.722 195.933,330.722 cw(c195.933,330.821) 195.833,330.821 195.833,331.019 cw(c195.933,331.019) 195.933,331.119 195.918,331.119 ccw(c195.918,331.169) 195.968,331.169 195.968,331.241 195.968,331.549 196.63,332.21 196.63,334.457 200.602,338.43 200.947,338.43 201.088,338.571 201.093,338.571 201.379,338.856 v15(201.646,338.856)
DDR4_A2: R35.1 U1.AK29 U8.R3 U9.R3 U10.R3 U11.R3 | length 99
  L1 w0.116: v4(170.472,339.664) U9.R3@170.876,339.26 ; v4(181.933,339.664) U11.R3@182.336,339.26 ; v6(190.909,316.052) U1.AK29@191.397,316.539 ; v4(193.393,339.664) U10.R3@193.797,339.26 ; v15(204.853,339.664) U8.R3@205.257,339.26
  L1 w0.155: v6(173.646,343.555) R35.1@173.646,344.8
  L5 (Sign) w0.092: v4(170.472,339.664) 170.901,339.664 171.305,340.068 172.536,340.068 173.449,340.981 180.235,340.981 180.335,340.881 cw(c180.276,340.822) 180.335,340.764 ccw(c180.398,340.701) 180.335,340.637 180.525,340.447 ccw(c180.588,340.511) 180.651,340.447 cw(c180.71,340.389) 180.768,340.447 181.326,339.89 181.552,339.664 v4(181.933,339.664) 182.433,339.664 182.837,340.068 183.672,340.068 184.891,341.287 186.792,341.287 186.987,341.287 cw(c186.987,341.218) 187.056,341.218 187.056,341.216 ccw(c187.125,341.216) 187.125,341.147 187.333,341.147 ccw(c187.333,341.216) 187.402,341.216 187.402,341.218 cw(c187.471,341.218) 187.471,341.287 187.748,341.287 187.922,341.287 188.299,341.287 cw(c188.299,341.218) 188.368,341.218 188.368,341.216 ccw(c188.437,341.216) 188.437,341.147 188.645,341.147 ccw(c188.645,341.216) 188.714,341.216 188.714,341.218 cw(c188.783,341.218) 188.783,341.287 188.887,341.287 191.389,341.287 193.012,339.664 v4(193.393,339.664) 193.822,339.664 194.226,340.068 195.277,340.068 195.516,340.307 195.516,340.906 196.164,341.554 196.913,341.554 197.164,341.554 ccw(c197.164,341.643) 197.254,341.643 197.254,341.758 cw(c197.344,341.758) 197.344,341.848 197.612,341.848 cw(c197.612,341.758) 197.702,341.758 197.702,341.554 197.702,341.349 ccw(c197.791,341.349) 197.791,341.26 198.06,341.26 ccw(c198.06,341.349) 198.15,341.349 198.15,341.554 198.15,341.658 cw(c198.239,341.658) 198.239,341.748 198.508,341.748 cw(c198.508,341.658) 198.597,341.658 198.597,341.554 198.597,341.349 ccw(c198.687,341.349) 198.687,341.26 198.956,341.26 ccw(c198.956,341.349) 199.045,341.349 199.045,341.554 199.045,341.658 cw(c199.135,341.658) 199.135,341.748 199.403,341.748 cw(c199.403,341.658) 199.493,341.658 199.493,341.554 199.493,341.349 ccw(c199.583,341.349) 199.583,341.26 199.851,341.26 ccw(c199.851,341.349) 199.941,341.349 199.941,341.464 cw(c200.03,341.464) 200.03,341.554 200.165,341.554 204.127,341.554 204.23,341.451 204.23,340.289 204.853,339.666 v15(204.853,339.664)
  L3 (Sign) w0.092: v4(170.472,339.664) 170.901,339.664 171.317,340.079 171.317,340.881 171.456,341.02 171.471,341.02 171.536,341.085 ; v6(190.909,316.052) 191.179,316.322 193.462,316.322 193.533,316.392 ccw(c193.462,316.462) 193.533,316.532 193.212,316.853 cw(c193.282,316.924) 193.212,316.994 193.352,317.134 cw(c193.422,317.064) 193.492,317.134 193.884,316.743 ccw(c193.954,316.813) 194.024,316.743 194.164,316.883 ccw(c194.094,316.953) 194.164,317.024 193.773,317.415 cw(c193.843,317.485) 193.773,317.555 193.913,317.696 cw(c193.984,317.625) 194.054,317.696 194.445,317.304 ccw(c194.515,317.374) 194.585,317.304 194.726,317.445 ccw(c194.656,317.515) 194.726,317.585 194.416,317.895 cw(c194.486,317.965) 194.416,318.035 194.556,318.175 cw(c194.627,318.105) 194.697,318.175 195.006,317.866 ccw(c195.077,317.936) 195.147,317.866 195.287,318.006 ccw(c195.217,318.076) 195.287,318.146 195.021,318.412 cw(c195.092,318.482) 195.021,318.553 195.162,318.693 cw(c195.232,318.623) 195.302,318.693 195.568,318.427 ccw(c195.638,318.497) 195.708,318.427 195.849,318.568 ccw(c195.778,318.638) 195.849,318.708 195.508,319.048 cw(c195.579,319.118) 195.508,319.188 195.649,319.329 cw(c195.719,319.259) 195.789,319.329 196.129,318.989 ccw(c196.199,319.059) 196.27,318.989 196.41,319.129 ccw(c196.34,319.199) 196.41,319.269 196.093,319.586 cw(c196.163,319.657) 196.093,319.727 196.233,319.867 cw(c196.304,319.797) 196.374,319.867 196.691,319.55 ccw(c196.761,319.62) 196.831,319.55 196.971,319.69 ccw(c196.901,319.761) 196.971,319.831 196.707,320.095 cw(c196.778,320.165) 196.707,320.235 196.848,320.376 cw(c196.918,320.305) 196.988,320.376 197.252,320.112 ccw(c197.322,320.182) 197.393,320.112 197.533,320.252 ccw(c197.463,320.322) 197.533,320.392 197.269,320.656 cw(c197.34,320.726) 197.269,320.796 197.41,320.936 cw(c197.48,320.866) 197.55,320.936 197.814,320.673 ccw(c197.884,320.743) 197.954,320.673 198.094,320.813 ccw(c198.024,320.884) 198.094,320.954 197.769,321.279 cw(c197.839,321.349) 197.769,321.419 197.909,321.56 cw(c197.98,321.489) 198.05,321.56 198.375,321.234 ccw(c198.445,321.305) 198.515,321.234 198.656,321.375 ccw(c198.586,321.445) 198.656,321.515 198.358,321.813 cw(c198.428,321.883) 198.358,321.953 198.499,322.093 cw(c198.569,322.023) 198.639,322.093 198.937,321.796 ccw(c199.007,321.866) 199.077,321.796 199.217,321.936 ccw(c199.147,322.006) 199.217,322.077 198.955,322.338 cw(c199.026,322.409) 198.955,322.479 199.096,322.619 cw(c199.166,322.549) 199.236,322.619 199.498,322.357 ccw(c199.568,322.427) 199.638,322.357 199.779,322.498 ccw(c199.708,322.568) 199.779,322.638 199.444,322.973 cw(c199.514,323.043) 199.444,323.113 199.584,323.253 cw(c199.654,323.183) 199.725,323.253 200.059,322.919 ccw(c200.13,322.989) 200.2,322.919 200.34,323.059 ccw(c200.27,323.129) 200.34,323.199 200.079,323.46 cw(c200.15,323.53) 200.079,323.6 200.22,323.741 cw(c200.29,323.671) 200.36,323.741 200.621,323.48 ccw(c200.691,323.55) 200.761,323.48 200.902,323.621 ccw(c200.831,323.691) 200.902,323.761 201.068,323.928 201.077,323.928 201.147,323.998 201.154,323.991 201.215,324.052 201.215,324.074 201.247,324.106 201.269,324.106 201.33,324.167 201.323,324.174 201.393,324.244 201.393,324.253 202.135,324.994 202.135,326.499 202.057,326.576 202.057,335.669 202.253,335.864 202.578,335.864 202.969,336.255 202.969,337.779 203.249,338.06 203.249,339.66 203.898,340.309 204.208,340.309 v15(204.853,339.664)
  L3 (Sign) w0.151: 171.536,341.085 173.63,343.18 173.63,343.539 v6(173.646,343.555)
